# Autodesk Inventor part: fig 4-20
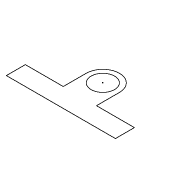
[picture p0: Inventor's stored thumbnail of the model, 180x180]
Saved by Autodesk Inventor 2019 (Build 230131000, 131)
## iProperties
Created: 2004-05
Part Number: fig 4-20
Document SubType Name: Modeling
Designer: CADCIM Technologies
Manufacturer: Standard
Standards Organization: Custom
Density: 1 g/cm^3
Material: Generic
Appearance: Default
Author: CADCIM Technologies
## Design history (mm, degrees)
sketch "Sketch1"
  geometry: L1 (21.396, 25)-(21.396, 15.181); L2 (21.396, 15.181)-(77.829, 15.181); L3 (77.829, 15.181)-(77.829, 25); L4 (77.829, 25)-(58.204, 25); L5 (58.204, 25)-(58.204, 36.886); L6 (41.021, 36.886)-(41.021, 25); L7 (41.021, 25)-(21.396, 25); C1 r 6.072 at (49.612, 36.886); A1 r 8.592 centre (49.612, 36.886) between (58.204, 36.886) and (41.021, 36.886)
  constraints: 14 end point, 5 parallel, 2 centre point, 2 equal length, 2 point on circle, 2 tangent, 1 coincident, 1 perpendicular, 1 vertical, 1 other
